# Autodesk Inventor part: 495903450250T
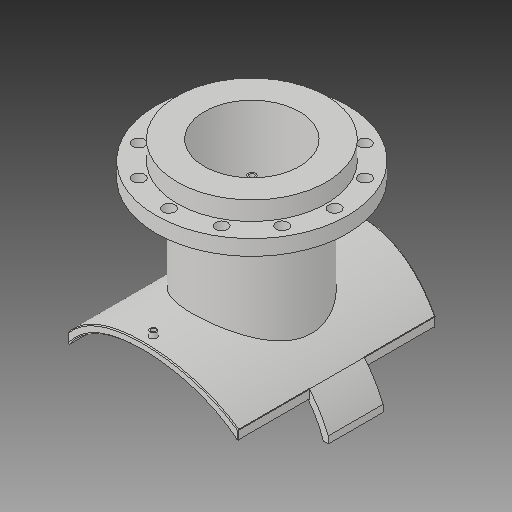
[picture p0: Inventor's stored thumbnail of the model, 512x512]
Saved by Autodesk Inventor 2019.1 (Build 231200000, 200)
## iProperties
Created: 2017-10
Part Number: 495903450250T
Material: Generic
Description: PLASSON FLANGED BRANCH SADDLE 450X250
Document SubType Name: Modeling
Designer: KIM
Mass: 2339.99 g
Surface Area: 3251.55 cm^2
Volume: 2339.99 cm^3
Density: 1 g/cm^3
Appearance: Default
Author: KIM
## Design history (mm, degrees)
derived "495904_495903.ipt"
feature "Solid1::495904_495903.ipt"
feature "Solid2::495904_495903.ipt"
tag "TaggingFeature1"
body "Solid1"
other parameters: "d1" = 15, "d2" = 364.5, "d4" = 0, "d6" = 117.5, "d7" = 0, "d12" = 250.6, "d13" = 14, "d14" = 211.5, "d16" = 5 deg, "d18" = 4, "d19" = 14, "d20" = 0, "d21" = 3, "d22" = 0, "d23" = 515, "d36" = 211.5, "d38" = 0, "d39" = 2, "d41" = 204, "d46" = 256, "d47" = 16, "d48" = 10.4, "d49" = 192.5, "d51" = 459, "d53" = 0, "d54" = 26, "d55" = 177.5, "d57" = 0, "d59" = 360 deg, "d61" = 33, "d63" = 0, "d66" = 275, "d67" = 15, "d68" = 137.5, "d70" = 0, "d71" = 2, "d72" = 405, "B_" = 405, "H_" = 275, "x_" = 15, "D_" = 16, "DN_" = 204, "t_" = 33, "s_" = 26, "Dp_" = 355
